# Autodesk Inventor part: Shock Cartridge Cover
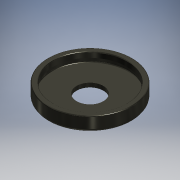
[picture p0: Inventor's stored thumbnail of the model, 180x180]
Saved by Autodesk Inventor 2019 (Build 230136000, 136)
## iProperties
Shininess: 50.0
Compacted: True
Length Units: 11272
Angle Units: 11279
Time Units: 11290
Mass Units: 11286
Length Display Precision: 4
Angle Display Precision: 2
Company: Autodesk
Created: 2000-03
Part Number: Shock Cartridge Cover
Project: Inventor Samples
User Status: IN PROGRESS
Document SubType Name: Modeling
Designer: Autodesk, Inc.
Density: 1.13 g/cm^3
Mass: 0.0672763 g
Surface Area: 2.56437 cm^2
Volume: 0.0595366 cm^3
Material: Nylon-6/6
Appearance: Gunmetal
Density: 0.0
Volumn: 0.0
Area: 0.0
PropertySet Name: Model Information
Control State: 0
Master: False
Checked Out: False
Checked Out Date: 2018-05-30
Last Check In Date: 2018-05-30
Author: Autodesk, Inc.
Revision Number: A
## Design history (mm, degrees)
node "Revolution1" dims "d8" = 90 deg
  sketch "Sketch2"
    geometry: L1 (-3.185, -5.855)-(-3.185, -11.958); L2 (-1.534, -9.15)-(-1.534, -9.658); L3 (-1.534, -9.658)-(2.022, -9.658); L4 (2.022, -9.658)-(2.022, -7.88); L5 (2.022, -7.88)-(1.387, -7.88); L6 (1.387, -7.88)-(1.333, -8.515); L7 (1.333, -8.515)-(1.577, -8.515); L8 (1.577, -8.515)-(1.577, -9.15); L9 (1.577, -9.15)-(-1.534, -9.15); L10 (1.587, -9.525)-(1.587, -8.89) reference
    constraints: 18 end point, 6 parallel, 1 perpendicular, 1 vertical, 1 other
    dimensions: "d0" = 10.414 diameter of L4 L1; "d1" = 3.302 diameter of L2 L1; "d2" = 9.525 diameter of L8 L1; "d3" = 0.508 distance between parallel lines of L3 L9; "d4" = 0.635 distance from line of L7.end L5; "d5" = 1.27 distance between parallel lines of L9 L5; "d6" = 0.635 distance of L4.end L5.end; "d7" = 0.254 horizontal distance of L10.start L6.end
node "Fillet1" dims "d9" = 0.381
node "Fillet2" dims "d10" = 0.127
body "Solid1"
